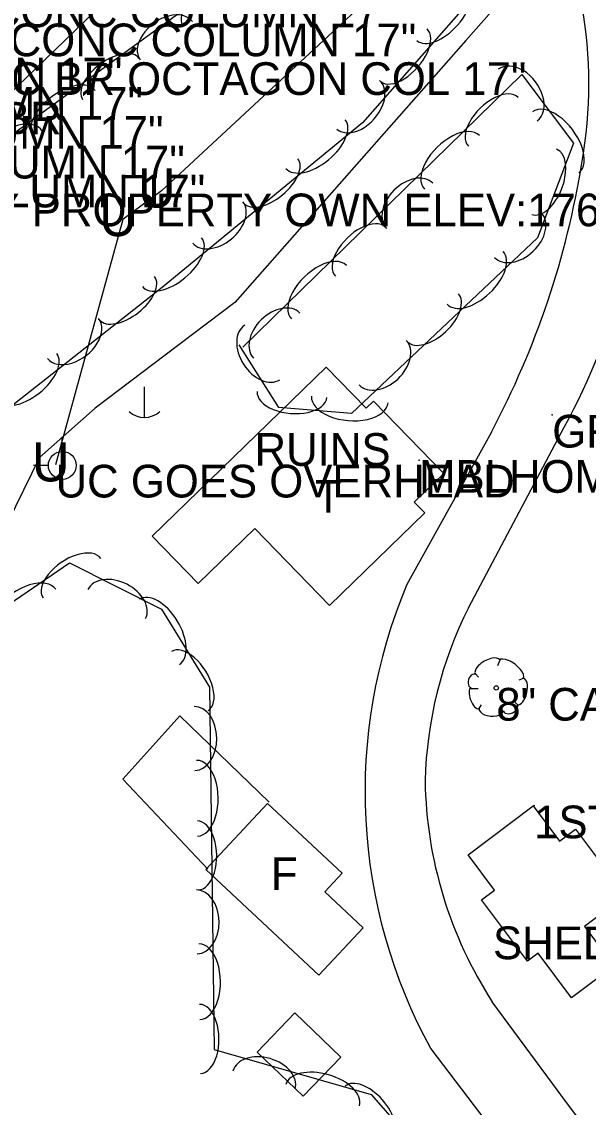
# Model space of a CAD drawing. Extents: x 1451369 to 1458940, y 1868647 to 1875095.
# Drawn here: x 1454557.9 to 1454644.6, y 1871458.6 to 1871624.7 of the extents above; entities that cross this region are included whole.
import ezdxf

# ---------------------------------------------------------------- set-up
doc = ezdxf.new("R2010")
doc.units = 0
for name, color, linetype in [('Default', 7, 'Continuous'), ('E_Const Align', 7, 'Continuous'), ('E_Property Line', 7, 'Continuous'), ('E_Proposed ROW and Easements', 7, 'Continuous'), ('E_Row Point', 7, 'Continuous'), ('E_ROW Point Number', 7, 'Continuous'), ('E_Survey Point Number', 7, 'Continuous'), ('S_BUILDING_ANNOT', 7, 'Continuous'), ('S_EXIST_ROW', 7, 'Continuous'), ('S_HIST_HIGH_WATER_ANNOT', 7, 'Continuous'), ('S_MISC_STRUCTURES_ANNOT', 7, 'Continuous'), ('S_PARKING', 7, 'Continuous'), ('S_SURVEY_TEXT_ANNOT', 7, 'Continuous'), ('S_TRAILS', 7, 'Continuous'), ('S_TREE_ANNOT', 7, 'Continuous'), ('S_UNDERGROUND_CABLE_ANNOT', 7, 'Continuous')]:
    doc.layers.add(name, color=color, linetype=linetype)

msp = doc.modelspace()

# ---------------------------------------------------------------- linework, layer by layer
at = {"layer": 'E_Const Align'}
for p, q in [((1454576.63, 1871568.84), (1454576.63, 1871564.11)), ((1454564.12, 1871558.91), (1454564.12, 1871561.16)), ((1454562.03, 1871556.78), (1454559.7, 1871556.78)), ((1454564.2, 1871552.36), (1454564.2, 1871554.69))]:
    msp.add_line(p, q, dxfattribs=at)
msp.add_circle((1454564.12, 1871556.8), 2.13, dxfattribs=at)
msp.add_arc((1454576.69, 1871567.54), 3.41, 226.3972, 313.6028, dxfattribs=at)
at = {"layer": 'E_Property Line'}
for p, q in [((1454573.4, 1871508.78), (1454582.08, 1871518.49)), ((1454582.08, 1871518.49), (1454595.75, 1871505.28)), ((1454586.4, 1871495.04), (1454573.4, 1871508.78))]:
    msp.add_line(p, q, dxfattribs=at)
for points in [[(1454577.87, 1871545.98), (1454604.49, 1871571.85), (1454610.6, 1871565.56), (1454611.71, 1871566.63), (1454622.47, 1871555.56), (1454617.96, 1871551.18), (1454619.55, 1871549.55), (1454604.98, 1871535.38), (1454593.55, 1871547.14), (1454584.91, 1871538.74)], [(1454603.36, 1871478.8), (1454586.06, 1871494.97), (1454595.51, 1871505.08), (1454606.94, 1871494.41), (1454604.27, 1871491.56), (1454610.15, 1871486.07)], [(1454626.18, 1871497.22), (1454636.15, 1871504.7), (1454640.18, 1871499.32), (1454642.63, 1871501.16), (1454650.27, 1871490.96), (1454644, 1871486.26), (1454648.52, 1871480.23), (1454642.03, 1871475.37), (1454636.93, 1871482.19), (1454635.27, 1871480.95), (1454628.23, 1871490.34), (1454630.22, 1871491.83)], [(1454599.69, 1871473.04), (1454606.71, 1871466.29), (1454600.97, 1871460.3), (1454593.94, 1871467.05)]]:
    msp.add_lwpolyline(points, close=True, dxfattribs=at)
at = {"layer": 'E_Proposed ROW and Easements'}
msp.add_lwpolyline([(1454639.06, 1871564.54), (1454639.06, 1871564.59), (1454639.06, 1871564.54), (1454639.01, 1871564.54), (1454639.06, 1871564.54), (1454639.06, 1871564.49), (1454639.06, 1871564.54), (1454639.11, 1871564.54)], dxfattribs=at)
at = {"layer": 'E_Row Point'}
for points in [[(1454618.7, 1871557.62), (1454618.7, 1871557.67), (1454618.7, 1871557.62), (1454618.65, 1871557.62), (1454618.7, 1871557.62), (1454618.7, 1871557.57), (1454618.7, 1871557.62), (1454618.75, 1871557.62)], [(1454636.29, 1871504.76), (1454636.29, 1871504.81), (1454636.29, 1871504.76), (1454636.24, 1871504.76), (1454636.29, 1871504.76), (1454636.29, 1871504.71), (1454636.29, 1871504.76), (1454636.34, 1871504.76)]]:
    msp.add_lwpolyline(points, dxfattribs=at)
at = {"layer": 'E_ROW Point Number'}
for p, q in [((1454631.06, 1871527), (1454630.67, 1871526.15)), ((1454627.26, 1871524.99), (1454627.77, 1871524.41)), ((1454634.63, 1871524.21), (1454633.97, 1871523.94)), ((1454626.61, 1871522.66), (1454627.73, 1871522.66)), ((1454627.77, 1871519.48), (1454628.23, 1871520.18)), ((1454631.45, 1871519.21), (1454631.37, 1871519.99)), ((1454633.85, 1871520.1), (1454633.39, 1871520.53))]:
    msp.add_line(p, q, dxfattribs=at)
for points in [[(1454466.05, 1871529.96), (1454507.82, 1871570.12), (1454546.16, 1871599.98), (1454595.25, 1871635.71), (1454622.47, 1871655.87), (1454630.45, 1871654.58), (1454632.33, 1871647.54), (1454628.1, 1871629.79), (1454610.02, 1871609.22), (1454579.17, 1871583.81), (1454543.54, 1871555.84), (1454533.41, 1871548.93), (1454494.55, 1871522.4), (1454482.82, 1871514.43), (1454469.55, 1871515.19), (1454464.89, 1871524.19), (1454466.39, 1871530.13)], [(1454591.72, 1871574.9), (1454634.41, 1871616.6), (1454642.33, 1871606.11), (1454636.83, 1871591.6), (1454608.36, 1871564.73), (1454597.26, 1871565.68), (1454591.17, 1871575.23)], [(1454479.99, 1871402.54), (1454460.24, 1871468.96), (1454473.6, 1871479.41), (1454519.69, 1871510.73), (1454565.25, 1871541.9), (1454579.31, 1871534.81), (1454586.65, 1871522.9), (1454587.34, 1871467.45), (1454611.35, 1871460.55), (1454622.55, 1871447.83)]]:
    msp.add_lwpolyline(points, dxfattribs=at)
msp.add_circle((1454630.5, 1871522.76), 0.341, dxfattribs=at)
for centre, major_axis, ratio, start_param, end_param in [((1454587.36, 1871627.43), (-4.73, -3.47), 0.531281, 3.133334, 6.274927), ((1454622.24, 1871626.22), (3.87, 4.41), 0.530273, 3.141649, 6.283241), ((1454580.02, 1871621.78), (-3.98, -2.95), 0.661859, 3.128451, 6.270044), ((1454616.38, 1871619.56), (3.53, 4.02), 0.521231, 3.141647, 6.28324), ((1454571.56, 1871615.93), (-4.31, -3.16), 0.522222, 3.133582, 6.275174), ((1454633.79, 1871613.46), (-2.99, 3.95), 0.685479, 3.141425, 6.283018), ((1454564.39, 1871610.72), (-4.73, -3.47), 0.531281, 3.133334, 6.274927), ((1454609.39, 1871611.99), (3.27, 3.72), 0.660635, 3.141681, 6.283274), ((1454630.05, 1871609.37), (-3.82, -3.74), 0.540705, 3.141594, 6.283187), ((1454639.58, 1871606.23), (-3.54, 4.68), 0.550215, 3.14149, 6.283083), ((1454602.86, 1871605.97), (4.53, 3.73), 0.530491, 3.141593, 6.283185), ((1454557.06, 1871605.07), (-3.98, -2.95), 0.661859, 3.128451, 6.270044), ((1454623.71, 1871603.18), (-4.2, -4.1), 0.550086, 3.141594, 6.283187), ((1454637.83, 1871600.21), (1.9, 5), 0.540697, 3.141593, 6.283185), ((1454596.01, 1871600.33), (4.13, 3.4), 0.521445, 3.141593, 6.283185), ((1454617.27, 1871596.52), (-3.54, -3.46), 0.685318, 3.141596, 6.283188), ((1454587.9, 1871593.98), (3.83, 3.15), 0.660906, 3.141593, 6.283185), ((1454633.81, 1871592.03), (3.6, 3.4), 0.685311, 3.141593, 6.283185), ((1454609.71, 1871589.51), (-3.82, -3.74), 0.540705, 3.141594, 6.283187), ((1454580.91, 1871587.9), (4.53, 3.73), 0.530491, 3.141593, 6.283185), ((1454603.37, 1871583.31), (-4.2, -4.1), 0.550086, 3.141594, 6.283187), ((1454627.26, 1871585.49), (4.27, 4.03), 0.55008, 3.141593, 6.283185), ((1454574.04, 1871582.39), (4.2, 3.31), 0.521606, 3.139187, 6.280779), ((1454620.81, 1871579.4), (3.89, 3.67), 0.540699, 3.141593, 6.283185), ((1454596.93, 1871576.66), (-3.54, -3.46), 0.685318, 3.141596, 6.283188), ((1454565.78, 1871576.22), (3.89, 3.07), 0.661107, 3.137649, 6.279242), ((1454594.71, 1871574.1), (2.67, -4.18), 0.6853, 3.141593, 6.283185), ((1454613.14, 1871572.52), (3.6, 3.4), 0.685311, 3.141593, 6.283185), ((1454558.65, 1871570.31), (4.61, 3.63), 0.530655, 3.139113, 6.280705), ((1454599.27, 1871567.64), (5.33, -0.45), 0.540698, 3.141603, 6.283196), ((1454608.1, 1871566.88), (5.85, -0.5), 0.550078, 3.141603, 6.283196), ((1454565.59, 1871539.56), (-4.41, -3.01), 0.541506, 3.141371, 6.282964), ((1454572.45, 1871535.6), (-4.42, 2.23), 0.685274, 3.141593, 6.283185), ((1454558.28, 1871534.56), (-4.84, -3.31), 0.5509, 3.141364, 6.282957), ((1454578.96, 1871531.34), (-3.07, 4.99), 0.550648, 3.142158, 6.28375), ((1454583.61, 1871523.8), (-2.8, 4.55), 0.541257, 3.14214, 6.283733), ((1454629.17, 1871525.96), (1.86, 1.08), 0.471018, 0, 3.141593), ((1454632.82, 1871525.64), (-1.81, 1.36), 0.405113, 3.141593, 6.283186), ((1454626.93, 1871523.84), (0.31, 1.03), 0.646762, 0, 3.141593), ((1454634.18, 1871522.23), (0.46, 2.04), 0.482994, 3.141593, 6.283185), ((1454627.24, 1871521.19), (-0.61, 1.6), 0.420543, 6.283185, 9.424777), ((1454584.36, 1871515.03), (-0.05, 4.89), 0.693958, 3.144846, 6.286438), ((1454632.66, 1871519.71), (1.09, 0.46), 0.711534, 3.141592, 6.283185), ((1454629.7, 1871519.41), (-1.83, 0.19), 0.529943, 0, 3.141593), ((1454584.74, 1871505.89), (-0.07, 5.79), 0.557022, 3.143555, 6.285148), ((1454584.85, 1871497.13), (-0.06, 5.28), 0.547523, 3.143493, 6.285086), ((1454584.71, 1871486.96), (-0.05, 4.89), 0.693958, 3.144846, 6.286438), ((1454585.09, 1871477.82), (-0.07, 5.79), 0.557022, 3.143555, 6.285148), ((1454585.2, 1871469.07), (-0.06, 5.28), 0.547523, 3.143493, 6.285086), ((1454594.98, 1871462.78), (-4.76, 1.37), 0.685289, 3.141593, 6.283185), ((1454603.95, 1871460.47), (-5.64, 1.62), 0.550062, 3.141593, 6.283185), ((1454610.93, 1871457.82), (-3.53, 4.01), 0.540647, 3.141593, 6.283185)]:
    msp.add_ellipse(centre, major_axis=major_axis, ratio=ratio, start_param=start_param, end_param=end_param, dxfattribs=at)
at = {"layer": 'E_Survey Point Number'}
for p, q in [((1454624.29, 1871640.62), (1454579.31, 1871598.81)), ((1454579.31, 1871598.81), (1454573.39, 1871594.42)), ((1454573.39, 1871594.42), (1454563.09, 1871556.9))]:
    msp.add_line(p, q, dxfattribs=at)
at = {"layer": 'S_EXIST_ROW'}
msp.add_lwpolyline([(1454637.64, 1871635.17), (1454625.86, 1871621.8), (1454614.08, 1871608.44), (1454602.3, 1871595.08), (1454590.52, 1871581.71), (1454579.84, 1871573.65), (1454569.16, 1871565.58), (1454560.65, 1871558.01), (1454555.73, 1871548.02), (1454536.22, 1871535.62)], dxfattribs=at)
at = {"layer": 'S_PARKING'}
for points in [[(1454629.75, 1871561.9), (1454616.8, 1871538.57)], [(1454626.27, 1871535.03), (1454640.89, 1871562.65)], [(1454667.4, 1871403.25), (1454691.79, 1871371.47), (1454711.91, 1871341.99), (1454726.42, 1871320.72), (1454730.31, 1871286), (1454750.1, 1871262.65), (1454771.52, 1871288.12), (1454747.41, 1871316.57), (1454731.99, 1871334.79), (1454698.75, 1871381.43), (1454674.92, 1871414.59), (1454641.56, 1871458.91), (1454629.89, 1871474.76)], [(1454620.49, 1871467.53), (1454648.64, 1871430.5), (1454640.49, 1871415.41), (1454646.62, 1871406.42)]]:
    msp.add_lwpolyline(points, dxfattribs=at)
for centre, major_axis, ratio, start_param, end_param in [((1454575.72, 1871615.11), (-28.7, 62.69), 0.999843, 4.107391, 4.814042), ((1454557.46, 1871609.88), (17.63, 95.75), 0.982787, 4.384696, 4.900665), ((1454513.05, 1871624.14), (33.23, 128.43), 0.996807, 4.476348, 4.805167), ((1454692.12, 1871506.83), (13.77, -80.65), 0.998436, 4.145162, 5.044569), ((1454681.09, 1871507.25), (-22.31, -57.45), 0.997175, 4.614107, 5.060738), ((1454683.61, 1871509.52), (40.93, -49.2), 0.999906, 4.033681, 4.592763)]:
    msp.add_ellipse(centre, major_axis=major_axis, ratio=ratio, start_param=start_param, end_param=end_param, dxfattribs=at)
at = {"layer": 'S_TRAILS'}
msp.add_lwpolyline([(1454633.14, 1871666.5), (1454620.4, 1871666.11), (1454609.48, 1871660.03), (1454584.95, 1871641.61), (1454552.82, 1871610.6), (1454495.73, 1871568.82), (1454476.2, 1871555.5), (1454470.45, 1871555.85), (1454464.28, 1871564.89), (1454461.53, 1871576.31)], dxfattribs=at)

# ---------------------------------------------------------------- texts
at = {"layer": 'Default'}
for p in [(1454575.68, 1871596.27), (1454569.76, 1871591.88), (1454559.46, 1871554.36)]:
    msp.add_text('U', height=6, rotation=360, dxfattribs=at).set_placement(p)
at = {"layer": 'S_BUILDING_ANNOT'}
for s, height, p in [('RUINS', 5, (1454593.53, 1871556.74)), ('MBLHOME W/ADDITION', 5, (1454618.7, 1871552.62)), ('T', 5, (1454602.76, 1871549.57)), ('1STRY WD STRGE SHED', 5, (1454636.29, 1871499.76)), ('F', 5, (1454596.03, 1871491.84)), ('SHED', 5.001, (1454630, 1871481.26))]:
    msp.add_text(s, height=height, dxfattribs=at).set_placement(p)
at = {"layer": 'S_HIST_HIGH_WATER_ANNOT'}
msp.add_text('HHW POINTED OUT BY PROPERTY OWN ELEV:176.57', height=5, dxfattribs=at).set_placement((1454483.3, 1871593.39))
at = {"layer": 'S_MISC_STRUCTURES_ANNOT'}
for p in [(1454517.22, 1871623.84), (1454520.42, 1871619.4), (1454475.47, 1871614.17), (1454478.62, 1871609.7), (1454481.76, 1871605.26), (1454485.02, 1871600.7), (1454488.14, 1871596.28)]:
    msp.add_text('OCTAGON CONC COLUMN 17"', height=5, dxfattribs=at).set_placement(p)
at = {"layer": 'S_SURVEY_TEXT_ANNOT'}
for s, p in [('10 SPAN STEEL/CONC BR OCTAGON COL 17"', (1454488.95, 1871613.48)), ('LOW STEEL ON BR', (1454502.72, 1871607.44)), ('GR DW ENT TO CAMP SITE', (1454639.06, 1871559.54))]:
    msp.add_text(s, height=5, dxfattribs=at).set_placement(p)
at = {"layer": 'S_TREE_ANNOT'}
msp.add_text('8" CATALPA', height=5, dxfattribs=at).set_placement((1454630.5, 1871517.76))
at = {"layer": 'S_UNDERGROUND_CABLE_ANNOT'}
msp.add_text('UC GOES OVERHEAD', height=5, dxfattribs=at).set_placement((1454563.09, 1871551.9))

doc.saveas('drawing.dxf')
